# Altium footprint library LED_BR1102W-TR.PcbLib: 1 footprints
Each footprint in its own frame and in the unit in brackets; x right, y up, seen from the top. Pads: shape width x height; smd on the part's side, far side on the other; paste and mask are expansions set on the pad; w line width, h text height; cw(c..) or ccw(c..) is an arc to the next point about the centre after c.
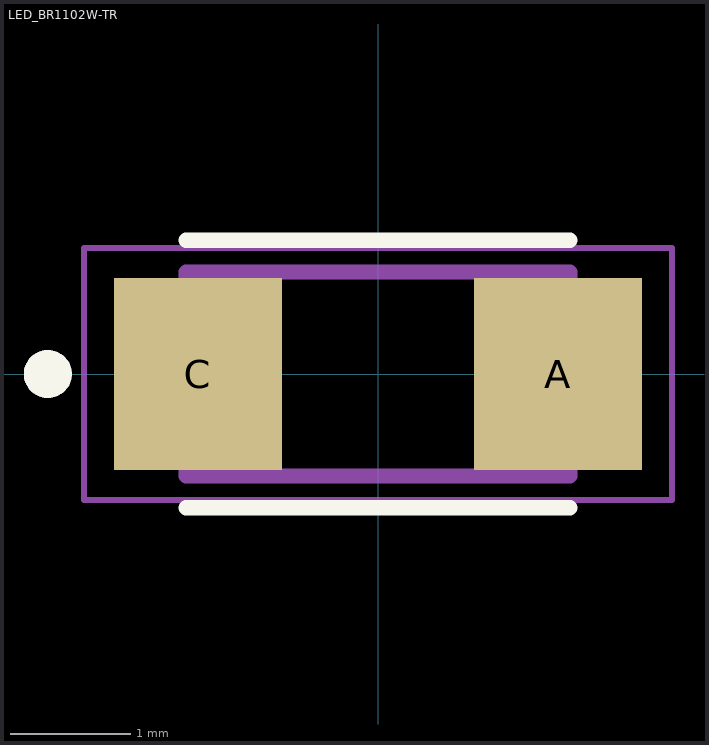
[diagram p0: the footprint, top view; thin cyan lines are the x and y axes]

## LED_BR1102W-TR [mm]
pads (2):
  rect 1.4x1.6 smd: A(1.5,0) C(-1.5,0)
Top Overlay:
  circle w0.2: c-2.75,0 r0.1
  lines w0.127: -1.6,-1.114 1.6,-1.114 ; -1.6,1.114 1.6,1.114
Mechanical 13:
  circle w0.2: c-2.75,0 r0.1
  lines w0.127: -1.6,-0.85 1.6,-0.85 1.6,0.85 -1.6,0.85 -1.6,-0.85
Mechanical 15:
  lines w0.05: -2.45,-1.05 2.45,-1.05 2.45,1.05 -2.45,1.05 -2.45,-1.05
